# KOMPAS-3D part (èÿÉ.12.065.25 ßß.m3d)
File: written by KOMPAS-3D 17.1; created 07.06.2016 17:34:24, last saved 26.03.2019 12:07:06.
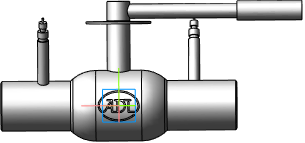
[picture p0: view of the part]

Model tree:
1. Операция без истории:5  (labels: Сталь 20  ГОСТ 1050-88)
